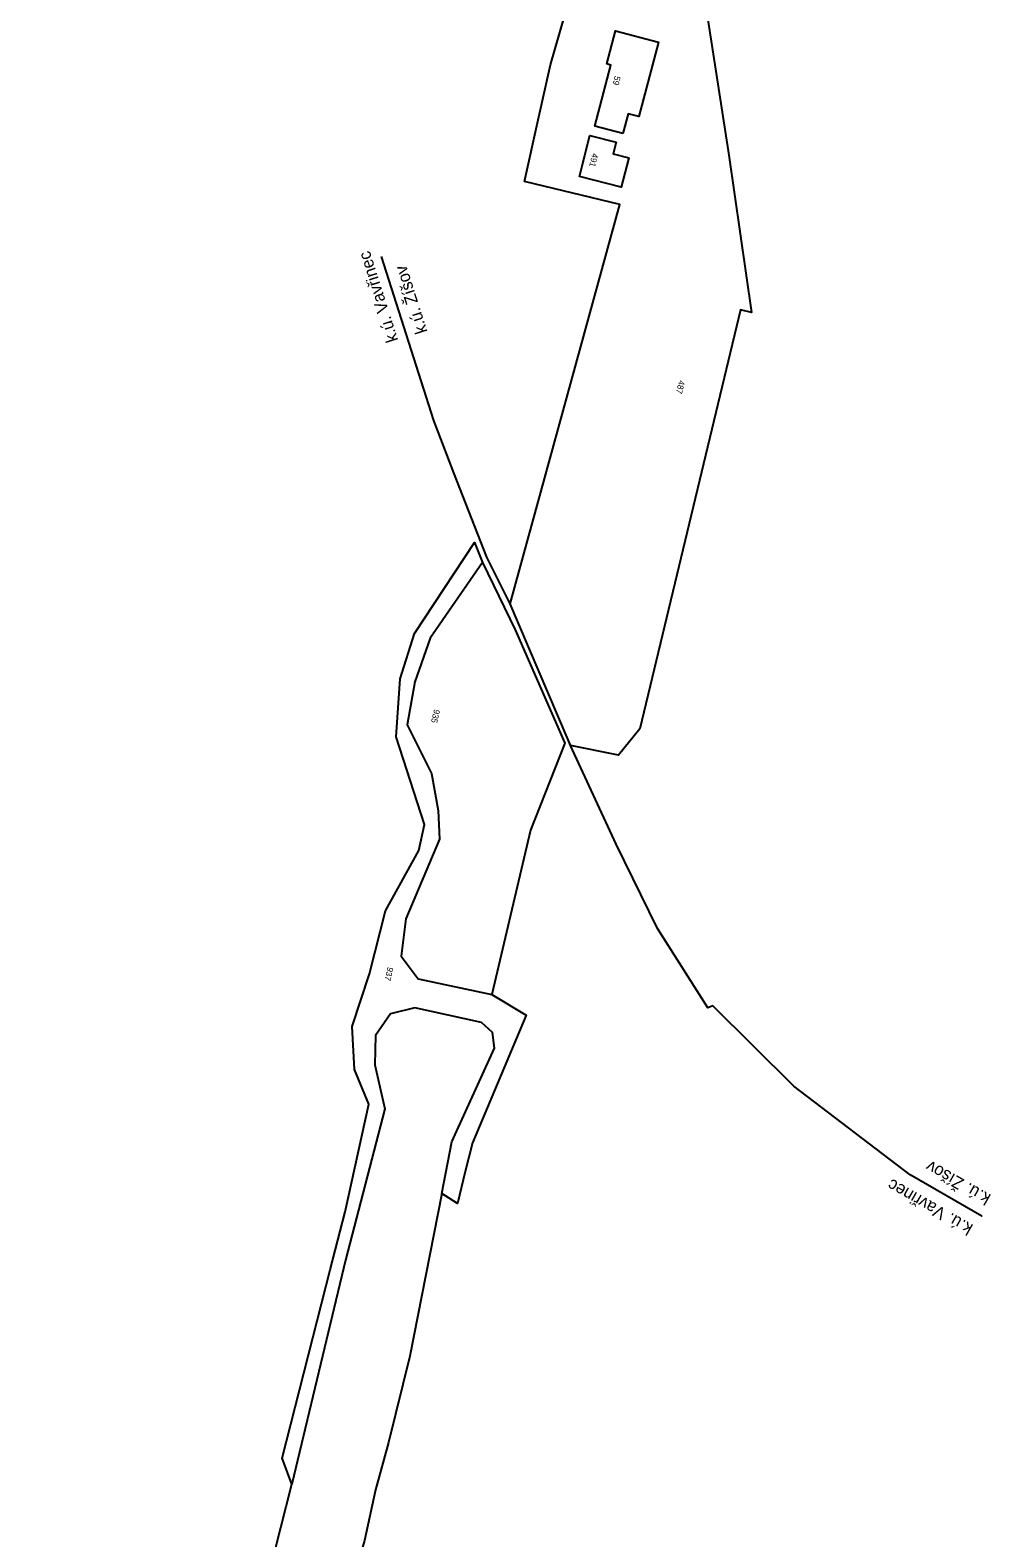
# Model space of a CAD drawing. Extents: x -700390 to -699853, y -1069116 to -1066813.
# Drawn here: x -700272.1 to -700036.4, y -1068543.8 to -1068173.9 of the extents above; entities that cross this region are included whole.
import ezdxf

# ---------------------------------------------------------------- set-up
doc = ezdxf.new("R2010")
doc.units = 0
for name, color, linetype in [('Vrstva 53', 7, 'Continuous'), ('Vrstva 55', 7, 'Continuous'), ('Vrstva 57', 7, 'Continuous')]:
    doc.layers.add(name, color=color, linetype=linetype)

msp = doc.modelspace()

# ---------------------------------------------------------------- linework, layer by layer
at = {"layer": 'Vrstva 53'}
for points in [[(-700139.57, -1068349.33), (-700140.37, -1068347.45), (-700154.33, -1068314.6), (-700127.48, -1068216.62), (-700150.86, -1068210.98), (-700147.46, -1068195.84), (-700144.44, -1068182.36), (-700139.73, -1068165.83), (-700138.06, -1068162.39), (-700136.01, -1068163.13), (-700128, -1068166.03), (-700125, -1068155.45), (-700122.97, -1068153.33), (-700118.3, -1068152.8), (-700112.98, -1068154.39)], [(-700112.98, -1068154.39), (-700106.34, -1068168.15), (-700100.69, -1068204.52), (-700095.19, -1068243.17), (-700097.88, -1068242.45), (-700122.52, -1068345.31), (-700127.75, -1068351.76), (-700139.55, -1068349.38), (-700139.57, -1068349.33)], [(-700272.12, -1068800.51), (-700246.17, -1068684.7), (-700237.75, -1068646.92), (-700221.56, -1068584.43), (-700207.93, -1068530.57), (-700210.28, -1068524.2), (-700198.49, -1068478.05), (-700194.85, -1068463.81), (-700189.02, -1068437.35), (-700192.53, -1068428.86), (-700193.12, -1068418.31), (-700188.9, -1068405.42), (-700184.91, -1068389.94), (-700176.8, -1068375.11), (-700175.39, -1068368.78), (-700182.31, -1068347.21), (-700181.37, -1068333.01), (-700177.85, -1068321.88), (-700163.08, -1068299.57), (-700161.14, -1068304.49)], [(-700161.14, -1068304.49), (-700153.1, -1068320.98), (-700140.98, -1068348.78), (-700149.35, -1068370.18), (-700158.83, -1068410.48), (-700150.45, -1068415.57), (-700163.64, -1068446.83), (-700165.37, -1068453.9), (-700167.28, -1068461.72), (-700171.14, -1068459.26), (-700178.95, -1068499.23), (-700184.18, -1068520.35), (-700187.39, -1068531.97), (-700190.09, -1068544.45), (-700194.37, -1068558.7), (-700194.83, -1068560.61), (-700197.02, -1068569.35), (-700223.59, -1068675.31), (-700254.95, -1068804.54), (-700261.58, -1068806.34), (-700266.43, -1068805.1), (-700272.12, -1068800.51)]]:
    msp.add_lwpolyline(points, dxfattribs=at)
at = {"layer": 'Vrstva 55'}
for points in [[(-700126.68, -1068199.23), (-700133.61, -1068197.41), (-700129.69, -1068182.42), (-700130.66, -1068182.17), (-700128.53, -1068174.04), (-700117.99, -1068176.8), (-700122.77, -1068195.08), (-700125.41, -1068194.39), (-700126.68, -1068199.23)], [(-700128.36, -1068201.35), (-700129.11, -1068204.22), (-700125.25, -1068205.22), (-700127.11, -1068212.42), (-700137.39, -1068209.76), (-700134.79, -1068199.69), (-700128.36, -1068201.35)], [(-700139.55, -1068349.38), (-700140.37, -1068347.45), (-700154.33, -1068314.6), (-700160.08, -1068303.17), (-700168.22, -1068282.49), (-700173.05, -1068269.66), (-700185.94, -1068229.39)], [(-700161.14, -1068304.49), (-700173.99, -1068323.05), (-700177.74, -1068333.72), (-700179.61, -1068344.27), (-700173.64, -1068356.23), (-700171.99, -1068365.31), (-700171.72, -1068372.34), (-700179.99, -1068391.86), (-700181.13, -1068401.03), (-700176.89, -1068406.64), (-700158.83, -1068410.48)], [(-700038.58, -1068464.86), (-700038.61, -1068464.81), (-700056.23, -1068454.74), (-700084.73, -1068432.94), (-700104.64, -1068413.25), (-700105.87, -1068413.73), (-700118.25, -1068394.29), (-700128.39, -1068373.62), (-700139.55, -1068349.38)], [(-700171.14, -1068459.26), (-700168.68, -1068446.6), (-700158.19, -1068423.65), (-700158.73, -1068419.8), (-700161.39, -1068417.33), (-700177.72, -1068413.75), (-700183.68, -1068415.22), (-700187.36, -1068420.52), (-700187.56, -1068427.75), (-700185.14, -1068438.49), (-700194.72, -1068475.62), (-700207.93, -1068530.57)]]:
    msp.add_lwpolyline(points, dxfattribs=at)

# ---------------------------------------------------------------- texts
for s, rotation, p in [('k.ú. Vavřinec', 107.7493, (-700181.79, -1068249.93)), ('k.ú. Žíšov', 107.7493, (-700174.62, -1068247.84)), ('k.ú. Žíšov', 150.2516, (-700036.2, -1068459.7)), ('k.ú. Vavřinec', 150.2516, (-700040.58, -1068467.08))]:
    msp.add_text(s, height=3, rotation=rotation, dxfattribs=at).set_placement(p)
at = {"layer": 'Vrstva 57'}
for s, rotation, p in [('59', 256.4578, (-700128.7, -1068184.99)), ('491', 256.4434, (-700134.2, -1068203.97)), ('487', 256.3888, (-700112.92, -1068259.65)), ('935', 256.4038, (-700173, -1068340.41)), ('937', 256.4077, (-700184.43, -1068403.63))]:
    msp.add_text(s, height=1.5, rotation=rotation, dxfattribs=at).set_placement(p)

doc.saveas('drawing.dxf')
